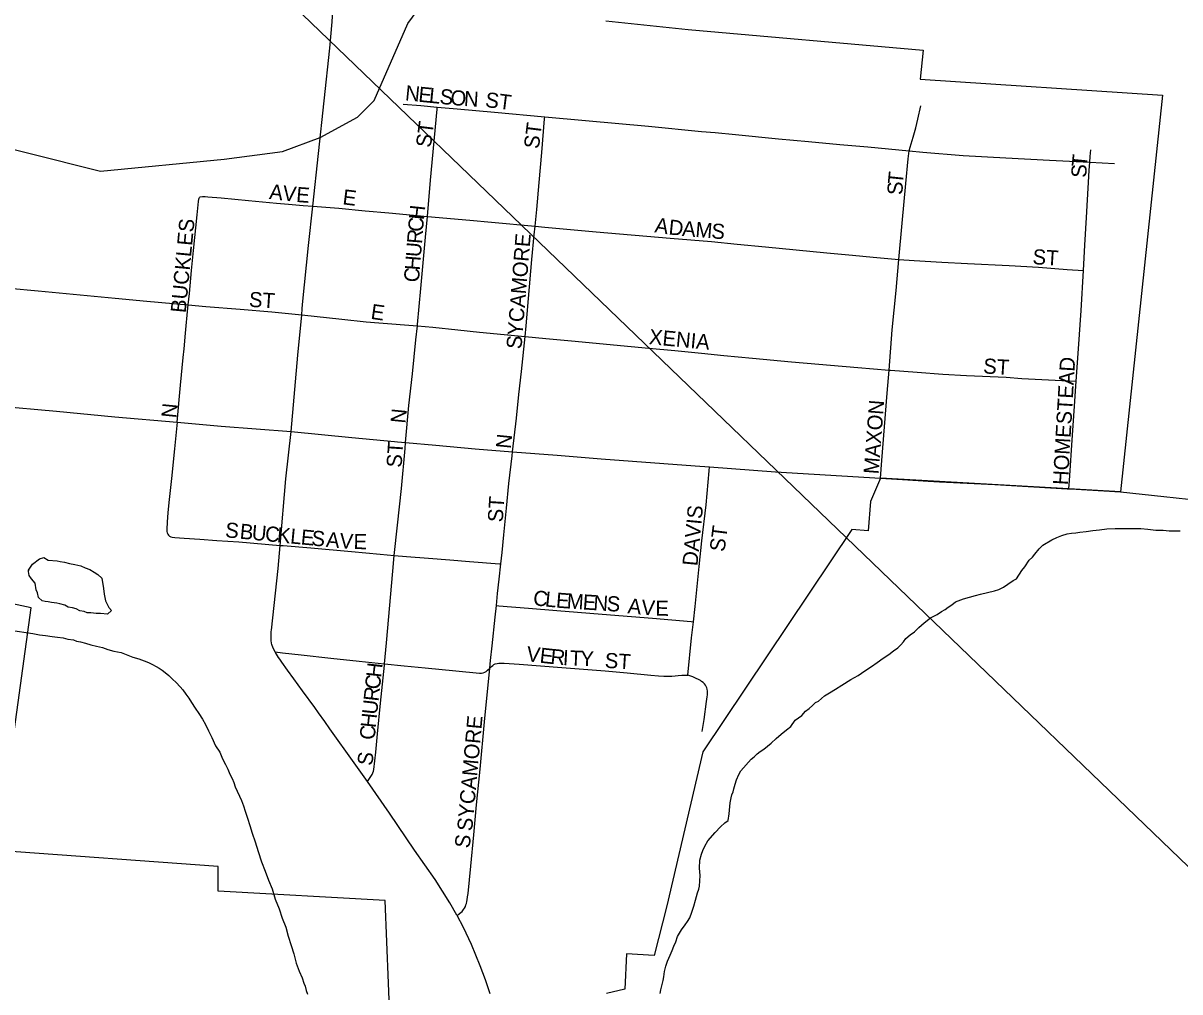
# Model space of a CAD drawing. Extents: x -49 to -8.2, y 9.4 to 23.5.
# Drawn here: x -44.3942 to -44.0326, y 18.6509 to 18.9539 of the extents above; entities that cross this region are included whole.
import ezdxf

# ---------------------------------------------------------------- set-up
doc = ezdxf.new("R2010")
doc.units = 0
for name, color, linetype in [('GM_X_City_Street', 7, 'Continuous'), ('GM_X_City_Street_Text', 7, 'Continuous'), ('GM_X_Corporation', 7, 'Continuous'), ('GM_X_Major_River', 7, 'Continuous'), ('GM_X_Minor_Lake', 7, 'Continuous'), ('GM_X_Minor_River', 7, 'Continuous'), ('GM_X_State_Route', 7, 'Continuous'), ('SC_Scratch1', 7, 'Continuous')]:
    doc.layers.add(name, color=color, linetype=linetype)

msp = doc.modelspace()

# ---------------------------------------------------------------- linework, layer by layer
at = {"layer": 'GM_X_City_Street'}
for points in [[(-44.27541, 18.92864), (-44.2699, 18.92816), (-44.26475, 18.9277)], [(-44.26785, 18.8935), (-44.26686, 18.90486), (-44.2648, 18.92708), (-44.26475, 18.9277)], [(-44.26475, 18.9277), (-44.25856, 18.92716), (-44.24681, 18.92611), (-44.23115, 18.92464)], [(-44.1172, 18.91398), (-44.1169, 18.91511), (-44.11597, 18.91825), (-44.11514, 18.92117), (-44.11448, 18.92394), (-44.11355, 18.92804)], [(-44.23416, 18.89039), (-44.23362, 18.89568), (-44.23287, 18.90414), (-44.23205, 18.91345), (-44.2312, 18.92404), (-44.23115, 18.92464)], [(-44.23115, 18.92464), (-44.21843, 18.92344), (-44.19875, 18.92169), (-44.1821, 18.92009), (-44.17786, 18.91969), (-44.17147, 18.91911), (-44.15811, 18.9178), (-44.14869, 18.91688), (-44.13887, 18.91601), (-44.13016, 18.91524), (-44.1172, 18.91398)], [(-44.1204, 18.88), (-44.11938, 18.89138), (-44.11824, 18.90381), (-44.11752, 18.91153), (-44.1172, 18.91398)], [(-44.1172, 18.91398), (-44.11289, 18.91356), (-44.10034, 18.9125), (-44.087, 18.91177), (-44.07332, 18.91106), (-44.06505, 18.91063), (-44.06076, 18.91041)], [(-44.06076, 18.91041), (-44.06061, 18.91219), (-44.06045, 18.91434)], [(-44.06274, 18.87661), (-44.0623, 18.88448), (-44.0618, 18.89318), (-44.06096, 18.90785), (-44.06076, 18.91041)], [(-44.06076, 18.91041), (-44.05304, 18.91001)], [(-44.3426, 18.86585), (-44.34225, 18.86941), (-44.34156, 18.87652), (-44.34098, 18.88282), (-44.33981, 18.89398), (-44.3394, 18.89816), (-44.33931, 18.8989), (-44.33921, 18.89916), (-44.33911, 18.89935), (-44.33884, 18.89956), (-44.33814, 18.89968), (-44.33732, 18.8997), (-44.33648, 18.89964), (-44.33228, 18.89926), (-44.32373, 18.89847), (-44.31501, 18.89768), (-44.31126, 18.89734), (-44.3067, 18.89693), (-44.30366, 18.89666)], [(-44.30366, 18.89666), (-44.29551, 18.89605), (-44.28729, 18.89525), (-44.27987, 18.89458), (-44.27001, 18.8937), (-44.26785, 18.8935)], [(-44.27097, 18.85922), (-44.27093, 18.85967), (-44.26992, 18.87092), (-44.26927, 18.87784), (-44.26842, 18.88697), (-44.26785, 18.8935)], [(-44.26785, 18.8935), (-44.25456, 18.89226), (-44.24783, 18.89165), (-44.23416, 18.89039)], [(-44.2373, 18.8559), (-44.237, 18.85927), (-44.23515, 18.87998), (-44.23444, 18.8877), (-44.23416, 18.89039)], [(-44.23416, 18.89039), (-44.23112, 18.89012), (-44.21508, 18.88864), (-44.19195, 18.88671), (-44.17904, 18.88563), (-44.17099, 18.88484), (-44.16211, 18.88397), (-44.1525, 18.88303), (-44.143, 18.88214), (-44.13489, 18.88138), (-44.12849, 18.88077), (-44.1204, 18.88)], [(-44.12351, 18.84543), (-44.12253, 18.85797), (-44.12127, 18.87034), (-44.1204, 18.88)], [(-44.1204, 18.88), (-44.1157, 18.87971), (-44.10702, 18.87922), (-44.09901, 18.8788), (-44.08599, 18.87812), (-44.07674, 18.87764), (-44.06783, 18.87691), (-44.06274, 18.87661)], [(-44.45726, 18.87585), (-44.44653, 18.87501), (-44.4395, 18.87444), (-44.42989, 18.87368), (-44.40779, 18.87191), (-44.38953, 18.87018), (-44.36551, 18.8679), (-44.3556, 18.86701), (-44.3426, 18.86585)], [(-44.06499, 18.842), (-44.06429, 18.8521), (-44.06345, 18.8641), (-44.06274, 18.87661)], [(-44.34608, 18.82912), (-44.34503, 18.84073), (-44.34415, 18.84934), (-44.34392, 18.85208), (-44.34347, 18.85693), (-44.3427, 18.86485), (-44.3426, 18.86585)], [(-44.3426, 18.86585), (-44.3371, 18.86535), (-44.32638, 18.86445), (-44.31647, 18.8636), (-44.30712, 18.86266)], [(-44.30712, 18.86266), (-44.2946, 18.86134), (-44.28698, 18.86055), (-44.28299, 18.86025), (-44.27097, 18.85922)], [(-44.27465, 18.82278), (-44.2736, 18.83432), (-44.27255, 18.8443), (-44.27143, 18.85493), (-44.27097, 18.85922)], [(-44.27097, 18.85922), (-44.26616, 18.85881), (-44.25834, 18.85797), (-44.25154, 18.8573), (-44.2373, 18.8559)], [(-44.24122, 18.8199), (-44.24, 18.83035), (-44.23922, 18.83781), (-44.23847, 18.84502), (-44.2373, 18.8559)], [(-44.2373, 18.8559), (-44.23077, 18.85525), (-44.22166, 18.85444), (-44.20966, 18.85335), (-44.19863, 18.85229), (-44.19048, 18.8515), (-44.18212, 18.85069), (-44.17521, 18.85003), (-44.16623, 18.84916), (-44.154, 18.84798), (-44.13329, 18.84623), (-44.12351, 18.84543)], [(-44.12615, 18.81157), (-44.12578, 18.8171), (-44.12408, 18.83816), (-44.12351, 18.84543)], [(-44.12351, 18.84543), (-44.12309, 18.8454), (-44.11473, 18.84473), (-44.1067, 18.84413), (-44.09928, 18.84374), (-44.08689, 18.84316), (-44.08194, 18.84282), (-44.06736, 18.84211), (-44.06499, 18.842)], [(-44.46039, 18.83963), (-44.45136, 18.83879), (-44.44057, 18.83778), (-44.4211, 18.83592), (-44.40257, 18.8342), (-44.38379, 18.83255), (-44.36556, 18.83082), (-44.34608, 18.82912)], [(-44.06727, 18.8083), (-44.06709, 18.81087), (-44.0661, 18.82505), (-44.06554, 18.83416), (-44.06499, 18.842)], [(-44.34608, 18.82912), (-44.34618, 18.82806), (-44.34692, 18.82082), (-44.34784, 18.81149), (-44.34853, 18.80492), (-44.34896, 18.80092), (-44.34924, 18.79783), (-44.34936, 18.79566), (-44.34932, 18.79495), (-44.34923, 18.79448), (-44.34903, 18.79407), (-44.34878, 18.79376), (-44.34847, 18.79347), (-44.3481, 18.79327), (-44.34763, 18.79314), (-44.34682, 18.79304), (-44.34387, 18.79284), (-44.33895, 18.7925), (-44.33369, 18.79215), (-44.32678, 18.79169), (-44.31389, 18.79059)], [(-44.34608, 18.82912), (-44.3323, 18.82793), (-44.31044, 18.82626)], [(-44.27824, 18.78747), (-44.27722, 18.79687), (-44.27598, 18.8084), (-44.27483, 18.82086), (-44.27465, 18.82278)], [(-44.24486, 18.7848), (-44.24444, 18.78832), (-44.24391, 18.79391), (-44.2431, 18.80224), (-44.24236, 18.8099), (-44.24136, 18.81864), (-44.24122, 18.8199)], [(-44.18466, 18.76672), (-44.18413, 18.77151), (-44.18368, 18.77564), (-44.18283, 18.78396), (-44.182, 18.79198), (-44.18072, 18.80327), (-44.17977, 18.81388), (-44.17966, 18.81516)], [(-44.31389, 18.79059), (-44.31297, 18.79051), (-44.3043, 18.78985), (-44.29153, 18.78864), (-44.28257, 18.78781), (-44.27824, 18.78747)], [(-44.28124, 18.75352), (-44.28066, 18.76016), (-44.27869, 18.78248), (-44.27824, 18.78747)], [(-44.27824, 18.78747), (-44.27433, 18.78715), (-44.26752, 18.78661), (-44.26086, 18.78607), (-44.25465, 18.78558), (-44.24528, 18.78484), (-44.24486, 18.7848)], [(-44.24628, 18.77177), (-44.24589, 18.77556), (-44.24543, 18.78), (-44.24486, 18.7848)], [(-44.24833, 18.75222), (-44.2481, 18.75457), (-44.24759, 18.75919), (-44.24666, 18.76819), (-44.24628, 18.77177)], [(-44.24628, 18.77177), (-44.2455, 18.7717), (-44.23628, 18.77095), (-44.22733, 18.77022), (-44.21059, 18.76886), (-44.19749, 18.76781), (-44.18538, 18.76678), (-44.18466, 18.76672)], [(-44.18645, 18.75002), (-44.18524, 18.76165), (-44.18466, 18.76672)], [(-44.31539, 18.75728), (-44.3131, 18.75701), (-44.30726, 18.75633), (-44.29801, 18.75532), (-44.28919, 18.75434), (-44.28124, 18.75352)], [(-44.28661, 18.71678), (-44.28577, 18.718), (-44.28515, 18.71889), (-44.28489, 18.71942), (-44.28471, 18.72), (-44.28462, 18.72051), (-44.28398, 18.72588), (-44.28342, 18.7316), (-44.28246, 18.74128), (-44.28128, 18.75313), (-44.28124, 18.75352)], [(-44.28124, 18.75352), (-44.27511, 18.75292), (-44.26851, 18.75227), (-44.25894, 18.75133), (-44.25151, 18.75061), (-44.25097, 18.75064), (-44.25037, 18.75075), (-44.24992, 18.75089), (-44.2495, 18.75117), (-44.24906, 18.75157), (-44.24834, 18.75222), (-44.24833, 18.75222)], [(-44.25853, 18.67483), (-44.25779, 18.67543), (-44.257, 18.6761), (-44.25655, 18.67666), (-44.25627, 18.67709), (-44.25596, 18.67769), (-44.2558, 18.67812), (-44.25563, 18.67857), (-44.25551, 18.67918), (-44.2554, 18.67976), (-44.25526, 18.68066), (-44.25512, 18.68175), (-44.25422, 18.69026), (-44.25331, 18.70005), (-44.25244, 18.70944), (-44.25134, 18.72057), (-44.24996, 18.73541), (-44.24833, 18.75222)], [(-44.24833, 18.75222), (-44.2478, 18.75266), (-44.24742, 18.75302), (-44.24704, 18.75333), (-44.24661, 18.75351), (-44.24602, 18.75365), (-44.2455, 18.75372), (-44.24504, 18.75375), (-44.2445, 18.75375), (-44.24386, 18.75373), (-44.23919, 18.75341), (-44.22579, 18.75239), (-44.21223, 18.75136), (-44.20542, 18.75077), (-44.19801, 18.75002), (-44.19555, 18.74977), (-44.19395, 18.74968), (-44.19248, 18.74964), (-44.19142, 18.7497), (-44.19033, 18.74974), (-44.18939, 18.74986), (-44.18833, 18.74995), (-44.18744, 18.75002), (-44.18645, 18.75002)], [(-44.18189, 18.73233), (-44.18133, 18.7361), (-44.18053, 18.74172), (-44.18036, 18.7432), (-44.18028, 18.74387), (-44.18025, 18.74452), (-44.18023, 18.74503), (-44.18035, 18.74563), (-44.18048, 18.74602), (-44.18069, 18.74649), (-44.18091, 18.74685), (-44.18122, 18.74725), (-44.18167, 18.74771), (-44.18214, 18.74805), (-44.18249, 18.74828), (-44.1829, 18.7485), (-44.18398, 18.74906), (-44.18488, 18.74945), (-44.18575, 18.7498), (-44.18645, 18.75002)]]:
    msp.add_lwpolyline(points, dxfattribs=at)
at = {"layer": 'GM_X_Corporation'}
for points in [[(-44.21204, 18.95461), (-44.18631, 18.95196), (-44.11286, 18.94551), (-44.11379, 18.93644), (-44.03803, 18.93136), (-44.05118, 18.80735), (-44.06727, 18.8083), (-44.12615, 18.81157), (-44.12929, 18.80431), (-44.13005, 18.79511), (-44.13518, 18.79551), (-44.18171, 18.72604), (-44.193, 18.67786), (-44.19692, 18.66232), (-44.20559, 18.66287), (-44.20614, 18.6518), (-44.21185, 18.65042)], [(-44.2795, 18.64073), (-44.28101, 18.67954), (-44.33321, 18.68246), (-44.33321, 18.69012), (-44.40226, 18.6952), (-44.3917, 18.77105), (-44.49365, 18.79297)]]:
    msp.add_lwpolyline(points, dxfattribs=at)
at = {"layer": 'GM_X_Major_River'}
msp.add_lwpolyline([(-44.41537, 18.91896), (-44.37001, 18.9076), (-44.33135, 18.91137), (-44.31314, 18.91384), (-44.30133, 18.91816), (-44.28966, 18.92457), (-44.28445, 18.92978), (-44.27394, 18.95386), (-44.26927, 18.96022)], dxfattribs=at)
at = {"layer": 'GM_X_Minor_Lake'}
msp.add_lwpolyline([(-44.39252, 18.78284), (-44.39136, 18.78472), (-44.38907, 18.78641), (-44.38774, 18.78677), (-44.38642, 18.786), (-44.38357, 18.78578), (-44.38263, 18.78557), (-44.3813, 18.78537), (-44.37979, 18.78497), (-44.37808, 18.78457), (-44.37714, 18.78437), (-44.37619, 18.78417), (-44.37487, 18.78359), (-44.37336, 18.783), (-44.37204, 18.78223), (-44.37091, 18.78145), (-44.36959, 18.7803), (-44.36906, 18.77706), (-44.36889, 18.77535), (-44.36853, 18.77326), (-44.36741, 18.77116), (-44.36666, 18.7702), (-44.36781, 18.76907), (-44.37009, 18.76929), (-44.37141, 18.7693), (-44.37312, 18.76951), (-44.37426, 18.76952), (-44.3752, 18.76991), (-44.37653, 18.77012), (-44.37766, 18.7707), (-44.3788, 18.77109), (-44.38012, 18.7713), (-44.38125, 18.77188), (-44.38277, 18.77228), (-44.38371, 18.77248), (-44.38542, 18.77269), (-44.38636, 18.77289), (-44.38731, 18.77309), (-44.38826, 18.77329), (-44.38939, 18.77425), (-44.38975, 18.77578), (-44.39012, 18.77673), (-44.39048, 18.77882), (-44.3916, 18.78017), (-44.39235, 18.78113), (-44.39252, 18.78246), (-44.39252, 18.78284), (-44.39252, 18.78265)], dxfattribs=at)
at = {"layer": 'GM_X_Minor_River'}
for points in [[(-44.07792, 18.78785), (-44.07658, 18.78954), (-44.07543, 18.79067), (-44.07256, 18.79234), (-44.07104, 18.79309), (-44.06951, 18.79364), (-44.0678, 18.79419), (-44.06647, 18.79437), (-44.06514, 18.79454), (-44.06381, 18.79472), (-44.06191, 18.79489), (-44.05982, 18.79524), (-44.05773, 18.79541), (-44.05545, 18.79576), (-44.05279, 18.79592), (-44.05071, 18.7959), (-44.04881, 18.79588), (-44.04691, 18.79586), (-44.04483, 18.79583), (-44.04255, 18.79562), (-44.04009, 18.7954), (-44.03781, 18.79537), (-44.03592, 18.79516), (-44.03421, 18.79514), (-44.0325, 18.79512)], [(-44.19391, 18.6556), (-44.1937, 18.65731), (-44.19331, 18.65901), (-44.19272, 18.66052), (-44.19233, 18.66147), (-44.19194, 18.66241), (-44.19136, 18.66393), (-44.19077, 18.66525), (-44.19019, 18.66657), (-44.1896, 18.66828), (-44.18844, 18.67035), (-44.18729, 18.67186), (-44.18652, 18.67299), (-44.18575, 18.67412), (-44.18516, 18.67582), (-44.18457, 18.67772), (-44.18398, 18.67961), (-44.18339, 18.68188), (-44.183, 18.68302), (-44.1828, 18.68397), (-44.18257, 18.68739), (-44.18274, 18.68967), (-44.18271, 18.69214), (-44.18212, 18.69403), (-44.18173, 18.69516), (-44.18115, 18.69649), (-44.18018, 18.69819), (-44.17787, 18.70082), (-44.17615, 18.70251), (-44.17481, 18.70383), (-44.17385, 18.70457), (-44.17345, 18.70666), (-44.17322, 18.71008), (-44.17283, 18.71159), (-44.17263, 18.71254), (-44.17224, 18.71349), (-44.17204, 18.71443), (-44.17164, 18.71595), (-44.17125, 18.71727), (-44.17047, 18.71897), (-44.16989, 18.72011), (-44.16663, 18.72368), (-44.16567, 18.72443), (-44.16471, 18.72537), (-44.16376, 18.72612), (-44.16261, 18.72687), (-44.16146, 18.7278), (-44.16032, 18.72874), (-44.15878, 18.73024), (-44.15725, 18.73156), (-44.15553, 18.73287), (-44.15419, 18.73399), (-44.15284, 18.73588), (-44.15074, 18.73737), (-44.14959, 18.73869), (-44.14844, 18.73962), (-44.14748, 18.74056), (-44.14652, 18.7415), (-44.14557, 18.74187), (-44.14365, 18.74356), (-44.14213, 18.74449), (-44.14022, 18.74561), (-44.13831, 18.74692), (-44.13544, 18.7486), (-44.13315, 18.7499), (-44.13105, 18.7514), (-44.12895, 18.7527), (-44.12723, 18.75401), (-44.12532, 18.75532), (-44.1236, 18.75644), (-44.12207, 18.75757), (-44.12073, 18.7585), (-44.11977, 18.75944), (-44.119, 18.76038), (-44.11823, 18.76151), (-44.11689, 18.76264), (-44.11555, 18.76357), (-44.11421, 18.76489), (-44.11249, 18.76639), (-44.11057, 18.76789), (-44.10848, 18.769), (-44.10714, 18.76994), (-44.10599, 18.77049), (-44.10504, 18.77124), (-44.10389, 18.77199), (-44.10274, 18.77293), (-44.10027, 18.77385), (-44.09836, 18.7744), (-44.09646, 18.77495), (-44.09494, 18.77531), (-44.09057, 18.7764), (-44.08923, 18.77676), (-44.08771, 18.77751), (-44.08637, 18.77844), (-44.08465, 18.77956), (-44.0837, 18.78012), (-44.08196, 18.78276), (-44.081, 18.78389), (-44.07965, 18.78597), (-44.07869, 18.7869), (-44.07792, 18.78785)], [(-44.39822, 18.76409), (-44.39121, 18.76306), (-44.38913, 18.76266), (-44.38723, 18.76245), (-44.38515, 18.76205), (-44.38345, 18.76184), (-44.38174, 18.76163), (-44.38023, 18.76123), (-44.37852, 18.76102), (-44.37758, 18.76063), (-44.37625, 18.76043), (-44.37474, 18.76003), (-44.37304, 18.75944), (-44.37133, 18.75904), (-44.36944, 18.75864), (-44.36774, 18.75805), (-44.36585, 18.75746), (-44.36358, 18.75705), (-44.3615, 18.75627), (-44.35999, 18.75568), (-44.3581, 18.75509), (-44.35639, 18.7545), (-44.35507, 18.75392), (-44.35375, 18.75333), (-44.35262, 18.75275), (-44.35168, 18.75217), (-44.35073, 18.75159), (-44.34979, 18.75082), (-44.34867, 18.74986), (-44.34754, 18.7487), (-44.34641, 18.74774), (-44.3451, 18.7464), (-44.34435, 18.74544), (-44.34342, 18.7441), (-44.34248, 18.74276), (-44.34155, 18.74142), (-44.34043, 18.7397), (-44.33931, 18.73797), (-44.33819, 18.73625), (-44.33726, 18.73453), (-44.33633, 18.73262), (-44.33521, 18.73052), (-44.3341, 18.72785), (-44.33279, 18.72593), (-44.33187, 18.72383), (-44.33094, 18.72211), (-44.33019, 18.72058), (-44.32964, 18.71906), (-44.3289, 18.71772), (-44.32834, 18.71638), (-44.32798, 18.71505), (-44.32594, 18.71085), (-44.32538, 18.70913), (-44.32483, 18.70741), (-44.3241, 18.70532), (-44.32336, 18.70303)], [(-44.32336, 18.70303), (-44.32263, 18.70055), (-44.32171, 18.69788), (-44.32079, 18.69483), (-44.31969, 18.69159), (-44.31858, 18.68873), (-44.31747, 18.68586), (-44.31636, 18.68319), (-44.31545, 18.67995), (-44.31415, 18.6769), (-44.31324, 18.67404), (-44.31213, 18.67118), (-44.3114, 18.66832), (-44.31048, 18.66546), (-44.30956, 18.66279), (-44.30883, 18.65993), (-44.30791, 18.65745), (-44.30698, 18.65535), (-44.30643, 18.65363), (-44.30606, 18.65268), (-44.3057, 18.65135), (-44.30533, 18.6502)], [(-44.1951, 18.65048), (-44.1949, 18.65162), (-44.19411, 18.65446), (-44.19391, 18.6556)]]:
    msp.add_lwpolyline(points, dxfattribs=at)
at = {"layer": 'GM_X_State_Route'}
for points in [[(-44.30697, 18.86463), (-44.30686, 18.86593), (-44.30497, 18.88436), (-44.30366, 18.89666), (-44.29838, 18.94614), (-44.29764, 18.95433), (-44.29739, 18.95789), (-44.2973, 18.95965), (-44.2976, 18.96381), (-44.29779, 18.96536)], [(-44.31044, 18.82626), (-44.30835, 18.8501), (-44.30712, 18.86266), (-44.30697, 18.86463)], [(-44.3166, 18.76405), (-44.31449, 18.78336), (-44.31389, 18.79059), (-44.31213, 18.81144), (-44.31044, 18.82626)], [(-44.31044, 18.82626), (-44.29144, 18.82438), (-44.27817, 18.8231), (-44.27714, 18.82301)], [(-44.27714, 18.82301), (-44.27465, 18.82278), (-44.26519, 18.8219), (-44.2529, 18.82083), (-44.24122, 18.8199), (-44.22732, 18.81878)], [(-44.22732, 18.81878), (-44.21352, 18.81768), (-44.18409, 18.81549), (-44.17966, 18.81516), (-44.15902, 18.81361), (-44.12615, 18.81157)], [(-44.12615, 18.81157), (-44.11767, 18.81105)], [(-44.11767, 18.81105), (-44.11124, 18.81066), (-44.10769, 18.81048)], [(-44.10769, 18.81048), (-44.09042, 18.80961), (-44.06777, 18.80833)], [(-44.06777, 18.80833), (-44.06727, 18.8083), (-44.06682, 18.80827), (-44.05118, 18.80735), (-44.03762, 18.8059), (-44.00673, 18.80252), (-43.98944, 18.80062), (-43.97524, 18.79893), (-43.96354, 18.79733), (-43.95728, 18.79648), (-43.95338, 18.79559), (-43.94949, 18.79453), (-43.94586, 18.79329), (-43.94293, 18.79214), (-43.94045, 18.79108), (-43.93806, 18.78993), (-43.93611, 18.78886)], [(-44.24824, 18.65029), (-44.24971, 18.65473), (-44.25134, 18.65911), (-44.2541, 18.66572), (-44.2566, 18.6711), (-44.25853, 18.67483), (-44.2586, 18.67498), (-44.26081, 18.67874), (-44.26546, 18.68612), (-44.27183, 18.69531), (-44.27967, 18.70688), (-44.28661, 18.71678), (-44.29071, 18.72263), (-44.29833, 18.7332), (-44.2999, 18.73548), (-44.30187, 18.73823), (-44.30307, 18.73991), (-44.30689, 18.74512), (-44.30963, 18.74883), (-44.31159, 18.75153), (-44.31335, 18.75403), (-44.31402, 18.75505), (-44.31435, 18.75556), (-44.31531, 18.75713), (-44.31539, 18.75728), (-44.31603, 18.75847), (-44.31649, 18.75955), (-44.31662, 18.76005), (-44.31672, 18.76084), (-44.3167, 18.76202), (-44.31665, 18.76361), (-44.3166, 18.76405)]]:
    msp.add_lwpolyline(points, dxfattribs=at)
at = {"layer": 'SC_Scratch1'}
msp.add_line((-49.03536, 23.5097), (-36.43741, 11.37924), dxfattribs=at)

# ---------------------------------------------------------------- texts
at = {"layer": 'GM_X_City_Street_Text'}
for s, height, rotation, p in [('N', 0.00473, 354.3068, (-44.27495, 18.92981)), ('E', 0.00473, 354.3084, (-44.27081, 18.92939)), ('L', 0.00473, 354.2813, (-44.26749, 18.92906)), ('S', 0.00473, 354.3007, (-44.26417, 18.92873)), ('O', 0.00473, 355.139, (-44.26078, 18.92839)), ('N', 0.00473, 356.3782, (-44.25652, 18.92803)), ('ST', 0.004735, 352.88, (-44.24993, 18.92772)), ('ST', 0.004735, 82.8783, (-44.26676, 18.91486)), ('ST', 0.004735, 82.8783, (-44.23301, 18.91445)), ('T', 0.00473, 84.2812, (-44.06172, 18.90879)), ('S', 0.00473, 89.0438, (-44.06177, 18.90557)), ('S', 0.00473, 88.8799, (-44.11927, 18.90015)), ('T', 0.00473, 84.2269, (-44.11921, 18.90338)), ('A', 0.00473, 353.626, (-44.31744, 18.89897)), ('V', 0.00473, 353.626, (-44.3133, 18.89851)), ('E', 0.00473, 355.4159, (-44.30899, 18.89803)), ('E', 0.00473, 352.8783, (-44.29452, 18.8973)), ('H', 0.00473, 83.9567, (-44.26894, 18.89223)), ('BUCKLES', 0.004735, 84.5223, (-44.34343, 18.86315)), ('C', 0.00473, 85.3573, (-44.26924, 18.88852)), ('A', 0.00473, 351.0012, (-44.19697, 18.88855)), ('D', 0.00473, 354.0337, (-44.19258, 18.88786)), ('A', 0.00473, 355.2182, (-44.18833, 18.88741)), ('M', 0.00473, 355.2507, (-44.18418, 18.88707)), ('S', 0.00473, 355.2533, (-44.17919, 18.88665)), ('R', 0.00473, 85.3648, (-44.26954, 18.88478)), ('SYCAMORE', 0.004735, 85.348, (-44.23844, 18.85185)), ('U', 0.00473, 85.3616, (-44.26988, 18.88063)), ('ST', 0.004735, 356.4254, (-44.07874, 18.87856)), ('H', 0.00473, 85.3531, (-44.27021, 18.87648)), ('C', 0.00473, 85.3573, (-44.27052, 18.87274)), ('ST', 0.004735, 356.4254, (-44.32374, 18.86522)), ('E', 0.00473, 351.8743, (-44.28575, 18.86147)), ('XENIA', 0.004735, 354.6138, (-44.19871, 18.85356)), ('ST', 0.004735, 356.4262, (-44.09416, 18.84439)), ('HOMESTEAD', 0.004735, 86.6723, (-44.0676, 18.80937)), ('MAXON', 0.004735, 85.5997, (-44.12677, 18.81274)), ('N', 0.00473, 84.2699, (-44.34635, 18.83026)), ('N', 0.00473, 84.2916, (-44.27468, 18.82859)), ('N', 0.00473, 84.2937, (-44.24176, 18.82067)), ('ST', 0.004735, 86.1879, (-44.27593, 18.81481)), ('ST', 0.004735, 86.4262, (-44.24427, 18.79772)), ('DAVIS', 0.004735, 84.5626, (-44.18343, 18.784)), ('S', 0.00473, 354.6102, (-44.33121, 18.79314)), ('B', 0.00473, 354.6018, (-44.32665, 18.79271)), ('U', 0.00473, 354.6156, (-44.32291, 18.79236)), ('C', 0.00473, 354.6011, (-44.31876, 18.79197)), ('K', 0.00473, 354.5982, (-44.31503, 18.79161)), ('L', 0.00473, 354.6052, (-44.31088, 18.79122)), ('E', 0.00473, 354.6102, (-44.30756, 18.79091)), ('ST', 0.004735, 82.88, (-44.17493, 18.78844)), ('S', 0.00473, 354.6102, (-44.30424, 18.79059)), ('A', 0.00473, 354.6088, (-44.29968, 18.79016)), ('V', 0.00473, 355.714, (-44.29543, 18.78976)), ('E', 0.00473, 359.2795, (-44.29096, 18.78944)), ('C', 0.00473, 354.0406, (-44.23495, 18.77189)), ('L', 0.00473, 354.2369, (-44.2312, 18.7715)), ('E', 0.00473, 355.5578, (-44.22777, 18.77115)), ('M', 0.00473, 356.3268, (-44.22437, 18.77089)), ('E', 0.00473, 356.3368, (-44.21938, 18.77057)), ('N', 0.00473, 356.3448, (-44.21605, 18.77035)), ('S', 0.00473, 356.3437, (-44.2119, 18.77009)), ('A', 0.00473, 354.1111, (-44.20536, 18.76939)), ('V', 0.00473, 355.4206, (-44.2011, 18.76895)), ('E', 0.00473, 359.2795, (-44.1966, 18.7686)), ('V', 0.00473, 353.7153, (-44.23703, 18.75439)), ('E', 0.00473, 353.7051, (-44.23289, 18.75393)), ('R', 0.00473, 354.3832, (-44.22951, 18.75356)), ('I', 0.00473, 356.7054, (-44.22558, 18.75317)), ('T', 0.00473, 357.5741, (-44.22342, 18.75305)), ('Y', 0.00473, 357.6814, (-44.22008, 18.75291)), ('ST', 0.004735, 356.4262, (-44.21249, 18.75231)), ('H', 0.00473, 83.6503, (-44.28231, 18.7491)), ('C', 0.00473, 83.6491, (-44.28273, 18.74537)), ('R', 0.00473, 83.6549, (-44.28314, 18.74164)), ('U', 0.00473, 83.6477, (-44.2836, 18.7375)), ('H', 0.00473, 83.9349, (-44.28404, 18.73336)), ('C', 0.00473, 86.3797, (-44.28427, 18.72967)), ('SYCAMORE', 0.004735, 84.8051, (-44.25385, 18.70107)), ('S', 0.00473, 82.8783, (-44.2851, 18.72153)), ('S', 0.00473, 82.8783, (-44.25468, 18.6957))]:
    msp.add_text(s, height=height, rotation=rotation, dxfattribs=at).set_placement(p)

doc.saveas('drawing.dxf')
